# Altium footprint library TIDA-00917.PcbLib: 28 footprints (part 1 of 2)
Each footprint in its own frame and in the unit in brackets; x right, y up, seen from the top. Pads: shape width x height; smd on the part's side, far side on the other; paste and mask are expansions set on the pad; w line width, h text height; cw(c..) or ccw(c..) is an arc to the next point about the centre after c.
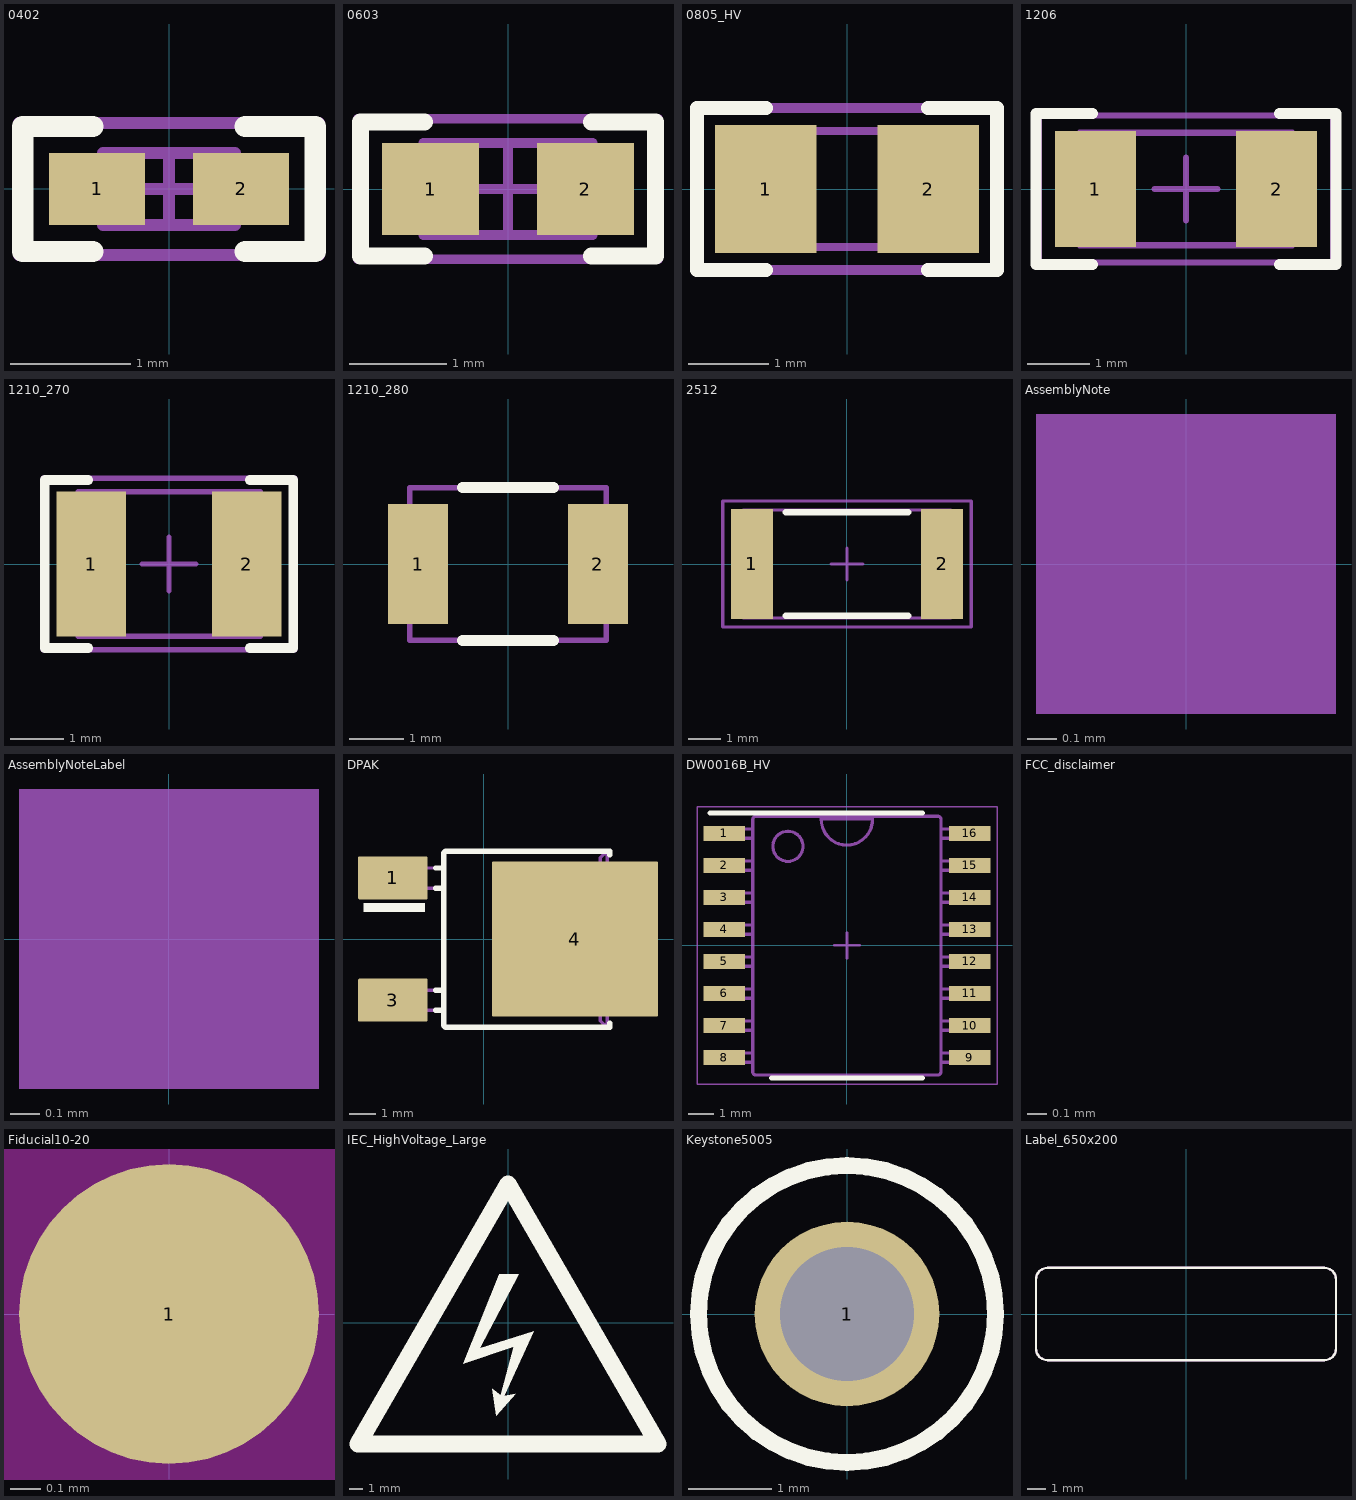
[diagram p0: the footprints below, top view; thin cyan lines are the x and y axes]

## 0402 [mm] "0402 from SM-752 data"
height 0.6
pads (2):
  rect 0.8x0.6 smd: 1(-0.6,0) 2(0.6,0)
Top Overlay:
  lines w0.178: -0.635,-0.521 -1.219,-0.521 -1.219,0.521 -0.635,0.521 ; 0.635,-0.521 1.219,-0.521 1.219,0.521 0.635,0.521
Mechanical 5:
  lines w0.1: -1.25,-0.55 -1.25,0.55 1.25,0.55 1.25,-0.55 -1.25,-0.55
  text ".Designator" at 3.659,0.291 h0.76
Mechanical 13:
  lines w0.1: -0.35,-0.3 -0.35,0.3 ; 0.35,-0.3 0.35,0.3 ; -0.55,-0.3 0.55,-0.3 0.55,0.3 -0.55,0.3 -0.55,-0.3
Mechanical 15:
  lines w0.1: -0.3,0 0.3,0 ; 0,-0.3 0,0.3 ; -1.25,-0.55 1.25,-0.55 1.25,0.55 -1.25,0.55 -1.25,-0.55
3D body: height 0.6, standoff 0, extent 0.351,-0.299 0.549,0.299
3D body: height 0.6, standoff 0, extent -0.349,-0.299 0.349,0.299
3D body: height 0.6, standoff 0, extent -0.549,-0.299 -0.351,0.299

## 0603 [mm] "0603 from SM-752 data"
height 1
pads (2):
  rect 1x0.95 smd: 1(-0.8,0) 2(0.8,0)
Top Overlay:
  lines w0.178: -0.864,-0.691 -1.524,-0.691 -1.524,0.693 -0.864,0.693 ; 0.864,-0.691 1.524,-0.691 1.524,0.693 0.864,0.693
Mechanical 5:
  lines w0.1: -1.55,-0.725 1.55,-0.725 1.55,0.725 -1.55,0.725 -1.55,-0.725
  text ".Designator" at 0.662,0.285 h0.76
Mechanical 13:
  lines w0.1: -0.55,-0.475 -0.55,0.475 ; 0.55,-0.475 0.55,0.475 ; -0.875,-0.475 -0.875,0.475 0.875,0.475 0.875,-0.475 -0.875,-0.475
Mechanical 15:
  lines w0.1: -0.475,0 0.475,0 ; 0,-0.475 0,0.475 ; -1.55,-0.725 -1.55,0.725 1.55,0.725 1.55,-0.725 -1.55,-0.725
3D body: height 1, standoff 0, extent 0.551,-0.474 0.874,0.474
3D body: height 1, standoff 0, extent -0.549,-0.474 0.549,0.474
3D body: height 1, standoff 0, extent -0.874,-0.474 -0.551,0.474

## 0805_HV [mil] "0805 with 30mil clearance between pads"
height 57.09
pads (2):
  rect 50x63 smd: 1(-40,0) 2(40,0)
Top Overlay:
  lines w7: -40,-40 -74,-40 -74,0 -74,40 -40,40 ; 40,-40 74,-40 74,0 74,40 40,40
Mechanical 5:
  lines w5: -74,-40 74,-40 74,40 -74,40 -74,-40
  text ".Designator" at -25.04,-16 h30
Mechanical 13:
  lines w3.94: -25.59,-28.54 -25.59,28.54 ; 25.59,-28.54 25.59,28.54 ; -43.31,-28.54 43.31,-28.54 43.31,28.54 -43.31,28.54 -43.31,-28.54
3D body: height 57.09, standoff 0, extent -43.29,-28.52 -25.61,28.52
3D body: height 57.09, standoff 0, extent -25.57,-28.52 25.57,28.52
3D body: height 57.09, standoff 0, extent 25.61,-28.52 43.29,28.52

## 1206 [mm] "1206 from SM-752 data"
height 1.35
pads (2):
  rect 1.3x1.85 smd: 1(-1.45,0) 2(1.45,0)
Top Overlay:
  lines w0.178: -1.5,-1.21 -2.4,-1.21 -2.4,1.21 -1.5,1.21 ; 1.5,-1.21 2.4,-1.21 2.4,1.21 1.5,1.21
Mechanical 5:
  lines w0.1: -1.7,-0.9 1.7,-0.9 1.7,0.9 -1.7,0.9 -1.7,-0.9
  text ".Designator" at -0.832,-0.306 h0.76
Mechanical 13:
  lines w0.1: -1.2,-0.9 -1.2,0.9 ; 1.2,-0.9 1.2,0.9 ; -1.7,-0.9 1.7,-0.9 1.7,0.9 -1.7,0.9 -1.7,-0.9
Mechanical 15:
  lines w0.1: -0.5,0 0.5,0 ; 0,-0.5 0,0.5 ; -2.35,-1.175 2.35,-1.175 2.35,1.175 -2.35,1.175 -2.35,-1.175
3D body: height 1.35, standoff 0, extent -1.699,-0.899 -1.201,0.899
3D body: height 1.35, standoff 0, extent -1.199,-0.899 1.199,0.899
3D body: height 1.35, standoff 0, extent 1.201,-0.899 1.699,0.899

## 1210_270 [mm] "1210"
height 2.7
pads (2):
  rect 1.3x2.7 smd: 1(-1.45,0) 2(1.45,0)
Top Overlay:
  lines w0.178: -1.511,-1.568 -2.316,-1.568 -2.316,1.568 -1.511,1.568 ; 1.511,-1.568 2.316,-1.568 2.316,1.568 1.511,1.568
Mechanical 5:
  lines w0.1: -1.7,-1.35 -1.7,1.35 1.7,1.35 1.7,-1.35 -1.7,-1.35
  text ".Designator" at 0.484,0.151 h0.76
Mechanical 13:
  lines w0.1: -1.2,-1.35 -1.2,1.35 ; 1.2,-1.35 1.2,1.35 ; -1.7,-1.35 1.7,-1.35 1.7,1.35 -1.7,1.35 -1.7,-1.35
Mechanical 15:
  lines w0.1: -0.5,0 0.5,0 ; 0,-0.5 0,0.5 ; -2.35,-1.6 2.35,-1.6 2.35,1.6 -2.35,1.6 -2.35,-1.6
3D body: height 2.7, standoff 0, extent 1.201,-1.349 1.699,1.349
3D body: height 2.7, standoff 0, extent -1.199,-1.349 1.199,1.349
3D body: height 2.7, standoff 0, extent -1.699,-1.349 -1.201,1.349

## 1210_280 [mm] "SMD, 2-Leads, Body 3.6x2.8mm, Height 2.8mm"
height 2.8
pads (2):
  rect 1.1x2.2 smd: 1(-1.65,0) 2(1.65,0)
Top Overlay:
  lines w0.2: -0.835,-1.4 0.835,-1.4 ; -0.835,1.4 0.835,1.4
Mechanical 5:
  lines w0.1: -1.8,-1.4 -1.8,1.4 1.8,1.4 1.8,-1.4 -1.8,-1.4
  text ".Designator" at 0.962,0.251 h0.76
3D body: height 2.8, standoff 0, extent -1.8,-1.4 -1.6,1.4
3D body: height 2.8, standoff 0, extent -1.6,-1.4 1.6,1.4
3D body: height 2.8, standoff 0, extent 1.6,-1.4 1.8,1.4

## 2512 [mm] "Chip Resistor, Body 6.3x3.2mm, IPC Medium Density"
height 0.71
pads (2):
  rect 1.3x3.4 smd: 1(-2.95,0) 2(2.95,0)
Top Overlay:
  lines w0.2: -1.9,-1.6 1.9,-1.6 ; -1.9,1.6 1.9,1.6
Mechanical 5:
  lines w0.1: -3.225,-1.675 -3.225,1.675 3.225,1.675 3.225,-1.675 -3.225,-1.675
  text ".Designator" at 0.697,0.38 h0.76
Mechanical 13:
  lines w0.1: -2.463,-1.675 -2.463,1.675 ; 2.463,-1.675 2.463,1.675 ; -3.225,-1.675 -3.225,1.675 3.225,1.675 3.225,-1.675 -3.225,-1.675
Mechanical 15:
  lines w0.1: -0.5,0 0.5,0 ; 0,-0.5 0,0.5 ; -3.85,-1.95 -3.85,1.95 3.85,1.95 3.85,-1.95 -3.85,-1.95
3D body: height 0.71, standoff 0, extent 2.464,-1.674 3.224,1.674
3D body: height 0.71, standoff 0, extent -2.462,-1.674 2.462,1.674
3D body: height 0.71, standoff 0, extent -3.224,-1.674 -2.464,1.674

## AssemblyNote [mm] "Assembly Note"
Mechanical 5:
  rectangle: -0.508,-0.508 0.508,0.508
  text ".Comment" at 1.143,-0.508 h0.76
  text ".Designator" at -4.191,-0.508 h0.76

## AssemblyNoteLabel [mm] "Assembly Note for PCB Labels"
Mechanical 5:
  rectangle: -0.508,-0.508 0.508,0.508
  text "Install label in silkscreened box after final wash.  Text shall be 8 pt font.  Text shall be per the Label Table in the PDF schematic." at 1.143,-0.508 h0.76
  text ".Designator" at -4.191,-0.508 h0.76

## DPAK [mm] "D-PAK, 3-Pads, Body 6.22x6.73mm (max), TO-252AA using nominal STEP model"
height 2.39
pads (3):
  rrect6% 2.6x1.6 smd: 1(-3.4,2.28) 3(-3.4,-2.28)
  rrect2% 6.2x5.8 smd paste-2.9: 4(3.4,0)
Top Overlay:
  rectangle: -4.5,1 -2.2,1.35
  lines w0.2: -1.8,1.9 -1.5,1.9 ; -1.8,2.65 -1.5,2.65 ; 4.7,-3.3 -1.429,-3.3 -1.5,-3.229 -1.5,-3.157 -1.5,-2.665 ; 4.7,-3.28 4.7,-3.15 ; 4.7,3.15 4.7,3.28 -1.429,3.28 -1.5,3.209 -1.5,3.137 -1.5,-1.915 ; -1.8,-2.665 -1.5,-2.665 ; -1.8,-2.665 -1.5,-2.665 ; -1.8,-2.665 -1.5,-2.665 ; -1.8,-1.915 -1.5,-1.915 ; -1.8,-1.915 -1.5,-1.915 ; -1.8,-1.915 -1.5,-1.915 ; -1.5,-2.665 -1.5,-1.915 ; -1.5,-2.665 -1.5,-1.915 ; -1.5,-2.665 -1.5,-1.915
Top Paste:
  rectangle: 0.4,-2.8 1.675,-1.625
  rectangle: 1.975,-2.8 3.25,-1.625
  rectangle: 3.55,-2.8 4.825,-1.625
  rectangle: 5.125,-2.8 6.4,-1.625
  rectangle: 5.125,-1.325 6.4,-0.15
  rectangle: 3.55,-1.325 4.825,-0.15
  rectangle: 1.975,-1.325 3.25,-0.15
  rectangle: 0.4,-1.325 1.675,-0.15
  rectangle: 5.125,0.15 6.4,1.325
  rectangle: 3.55,0.15 4.825,1.325
  rectangle: 1.975,0.15 3.25,1.325
  rectangle: 0.4,0.15 1.675,1.325
  rectangle: 5.125,1.625 6.4,2.8
  rectangle: 3.55,1.625 4.825,2.8
  rectangle: 1.975,1.625 3.25,2.8
  rectangle: 0.4,1.625 1.675,2.8
Mechanical 5:
  lines w0.127: -1.5,1.9 -2.757,1.9 -3.157,1.9 ; -1.5,2.65 -2.757,2.65 -3.157,2.65 ; -3.899,-2.665 -3.899,-1.915 ; -3.899,-2.665 -3.357,-2.665 ; -3.899,-2.665 -3.899,-1.915 ; -3.899,-2.665 -3.357,-2.665 ; -3.899,-2.665 -3.899,-1.915 ; -3.899,-2.665 -3.357,-2.665 ; -3.899,-1.915 -3.357,-1.915 ; -3.899,-1.915 -3.357,-1.915 ; -3.899,-1.915 -3.357,-1.915 ; -3.357,-2.665 -3.157,-2.665 ; -3.357,-2.665 -3.157,-2.665 ; -3.357,-2.665 -3.157,-2.665 ; -3.357,-1.915 -3.157,-1.915 ; -3.357,-1.915 -3.157,-1.915 ; -3.357,-1.915 -3.157,-1.915 ; -3.157,-2.665 -2.757,-2.665 ; -3.157,-2.665 -3.157,-1.915 ; -3.157,-2.665 -2.757,-2.665 ; -3.157,-2.665 -3.157,-1.915 ; -3.157,-2.665 -2.757,-2.665 ; -3.157,-2.665 -3.157,-1.915 ; -3.157,-1.915 -2.757,-1.915 ; -3.157,-1.915 -2.757,-1.915 ; -3.157,-1.915 -2.757,-1.915 ; -3.157,1.9 -3.157,2.65 ; -3.157,1.9 -3.357,1.9 -3.899,1.9 -3.899,2.65 -3.357,2.65 -3.157,2.65 ; -2.757,-2.665 -1.5,-2.665 ; -2.757,-2.665 -1.5,-2.665 ; -2.757,-2.665 -1.5,-2.665 ; -2.757,-1.915 -1.5,-1.915 ; -2.757,-1.915 -1.5,-1.915 ; -2.757,-1.915 -1.5,-1.915 ; -1.5,-2.665 -1.5,-3.157 -1.5,-3.229 -1.429,-3.3 4.6,-3.3 ; -1.5,-2.665 -1.5,-1.915 ; -1.5,-2.665 -1.5,-1.915 ; -1.5,-2.665 -1.5,-1.915 ; -1.5,-1.915 -1.5,3.137 -1.5,3.209 -1.429,3.28 4.6,3.28 ; 4.6,-3.3 4.348,-3.048 4.348,3.028 4.6,3.28 ; 4.6,-3.3 4.6,-2.69 5.8,-2.69 5.8,-2.01 5.308,-2.01 5.308,1.99 5.8,1.99 5.8,2.67 4.6,2.67 4.6,3.28
  text ".Designator" at 1.462,0.458 h0.76
3D body "td03b.stp": height 2.48, standoff 0.01, extent -3.856,-3.29 5.843,3.29

## DW0016B_HV [mm] "High voltage version of DW0016B"
height 2.64
pads (16):
  rect 1.65x0.6 smd: 1(-4.875,4.445) 2(-4.875,3.175) 3(-4.875,1.905) 4(-4.875,0.635) 5(-4.875,-0.635) 6(-4.875,-1.905) 7(-4.875,-3.175) 8(-4.875,-4.445) 9(4.875,-4.445) 10(4.875,-3.175) 11(4.875,-1.905) 12(4.875,-0.635) 13(4.875,0.635) 14(4.875,1.905) 15(4.875,3.175) 16(4.875,4.445)
Top Overlay:
  lines w0.2: -5.425,5.25 3,5.25 ; -3,-5.25 3,-5.25
Mechanical 5:
  drawing of 193 lines, arcs and shapes, not listed
  text ".Designator" at 0.528,0.535 h0.76
Mechanical 15:
  lines w0.05: -5.95,-5.5 -5.95,5.5 5.95,5.5 5.95,-5.5 -5.95,-5.5
  lines w0.1: -0.5,0 0.5,0 ; 0,-0.5 0,0.5
3D body "DW0016AakaM16B.stp": height 2.5, standoff -0.04, extent -5.144,-5.131 5.143,5.131

## FCC_disclaimer [mm]
Top Overlay:
  text "For evaluation only; not FCC approved for resale." at 52.781,98.629 h1.52

## Fiducial10-20 [mm]
pads (1):
  round 1 smd mask+0.5: 1(0,0)
Top Layer keep-out:
  circle w1.178: c0,0 r0.5

## IEC_HighVoltage_Large [mm]
height 17.5
Top Overlay:
  region: -0.635,3.556 0.787,3.556 -2.083,-1.88 1.905,-0.66 -0.279,-5.385 0.559,-5.232 -0.864,-6.858 -1.168,-4.877 -0.533,-5.359 0.432,-1.778 -3.302,-3.023
  lines w1.27: -11.049,-8.941 11.049,-8.941 0,10.197 -11.049,-8.941

## Keystone5005 [mil] "Keystone Compact loops"
height 220
pads (1):
  round 87 hole 63: 1(0,0)
Top Overlay:
  circle w7.99: c0,0 r70
Mechanical 5:
  circle w5: c0,0 r70.71
  text ".Designator" at -15.45,47.04 h30
3D body "Keystone_5005.stp": height 225.2, standoff -129.92, extent -63,-63 62.49,62.74

## Label_650x200 [mil] "Thermal Transfer Label"
height 1
pads (1):
  round 1 on Mech13: 0(0,0)
Top Overlay:
  lines w5: -325,-75 ccw(c-300,-75) -300,-100 300,-100 ccw(c300,-75) 325,-75 325,75 ccw(c300,75) 300,100 -300,100 ccw(c-300,75) -325,75 -325,-75
Mechanical 5:
  lines w5: -325,-75 ccw(c-300,-75) -300,-100 300,-100 ccw(c300,-75) 325,-75 325,75 ccw(c300,75) 300,100 -300,100 ccw(c-300,75) -325,75 -325,-75
  text ".Designator" at 25,5 h30
3D body: height 1, standoff 0, extent -325.02,-100.02 325.02,100.02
